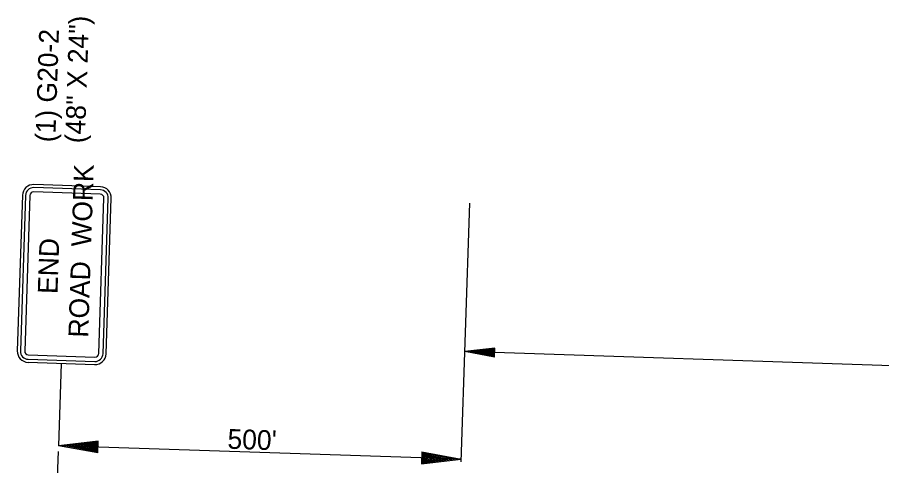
# Model space of a CAD drawing. Extents: x 977269 to 979191, y 1525946 to 1526973.
# Drawn here: x 977812.6 to 978075.3, y 1526710.3 to 1526846.4 of the extents above; entities that cross this region are included whole.
import ezdxf

# ---------------------------------------------------------------- set-up
doc = ezdxf.new("R2010")
doc.units = 0
for name, color, linetype in [('R_Border', 7, 'Continuous'), ('STAMP', 7, 'Continuous'), ('STAMP_PP', 7, 'Continuous')]:
    doc.layers.add(name, color=color, linetype=linetype)

msp = doc.modelspace()

# ---------------------------------------------------------------- linework, layer by layer
at = {"layer": 'STAMP'}
for p, q in [((977947.46, 1526711.49), (977950.08, 1526789.97)), ((977957.68, 1526745.99), (977948.57, 1526744.93)), ((977957.59, 1526743.27), (977948.57, 1526744.93)), ((978256.53, 1526734.66), (977948.57, 1526744.93)), ((977957.67, 1526745.76), (977950.09, 1526744.88)), ((977957.6, 1526743.5), (977950.09, 1526744.88)), ((977957.67, 1526745.53), (977951.65, 1526744.83)), ((977957.61, 1526743.73), (977951.65, 1526744.83)), ((977957.66, 1526745.3), (977953.15, 1526744.78)), ((977957.61, 1526743.95), (977953.15, 1526744.78)), ((977957.65, 1526745.07), (977954.69, 1526744.73)), ((977957.62, 1526744.19), (977954.69, 1526744.73)), ((977957.64, 1526744.84), (977956.2, 1526744.68)), ((977957.63, 1526744.42), (977956.2, 1526744.68)), ((977957.59, 1526743.27), (977957.68, 1526745.99)), ((977826.01, 1526741.35), (977825.18, 1526716.36)), ((977837.2, 1526717.76), (977825.18, 1526716.36)), ((977947.49, 1526712.28), (977825.18, 1526716.36)), ((977837.08, 1526714.17), (977825.18, 1526716.36)), ((977837.19, 1526717.46), (977827.18, 1526716.3)), ((977837.09, 1526714.47), (977827.18, 1526716.3)), ((977837.18, 1526717.15), (977829.24, 1526716.23)), ((977837.1, 1526714.77), (977829.24, 1526716.23)), ((977837.17, 1526716.86), (977831.23, 1526716.16)), ((977837.11, 1526715.07), (977831.23, 1526716.16)), ((977837.16, 1526716.55), (977833.26, 1526716.09)), ((977837.12, 1526715.38), (977833.26, 1526716.09)), ((977837.15, 1526716.24), (977835.25, 1526716.03)), ((977837.13, 1526715.68), (977835.25, 1526716.03)), ((977837.08, 1526714.17), (977837.2, 1526717.76)), ((977824.68, 1526701.15), (977825.13, 1526714.6)), ((977935.58, 1526714.48), (977935.46, 1526710.89)), ((977935.53, 1526712.96), (977937.41, 1526712.62)), ((977935.54, 1526713.26), (977939.41, 1526712.55)), ((977935.55, 1526713.57), (977941.44, 1526712.49)), ((977935.56, 1526713.87), (977943.43, 1526712.42)), ((977935.57, 1526714.18), (977945.49, 1526712.35)), ((977935.58, 1526714.48), (977947.49, 1526712.28)), ((977935.46, 1526710.89), (977947.49, 1526712.28)), ((977935.47, 1526711.19), (977945.49, 1526712.35)), ((977935.48, 1526711.49), (977943.43, 1526712.42)), ((977935.49, 1526711.79), (977941.44, 1526712.49)), ((977935.5, 1526712.1), (977939.41, 1526712.55)), ((977935.51, 1526712.4), (977937.41, 1526712.62))]:
    msp.add_line(p, q, dxfattribs=at)
at = {"layer": 'STAMP_PP'}
for p, q in [((977837.9, 1526794.05), (977817.66, 1526794.72)), ((977837.93, 1526794.98), (977817.69, 1526795.66)), ((977814.21, 1526792.4), (977812.63, 1526745.17)), ((977815.15, 1526792.37), (977813.57, 1526745.14)), ((977816.46, 1526792.32), (977814.88, 1526745.1)), ((977837.86, 1526792.73), (977817.62, 1526793.41)), ((977837.37, 1526744.35), (977838.95, 1526791.57)), ((977838.68, 1526744.3), (977840.26, 1526791.53)), ((977839.62, 1526744.27), (977841.19, 1526791.5)), ((977815.89, 1526741.69), (977836.13, 1526741.01)), ((977815.93, 1526742.62), (977836.16, 1526741.95)), ((977815.97, 1526743.94), (977836.21, 1526743.26))]:
    msp.add_line(p, q, dxfattribs=at)
for centre, radius, start, end in [((977817.58, 1526792.28), 3.37, 88.0901, 178.0901), ((977817.58, 1526792.28), 2.44, 88.0901, 178.0901), ((977837.82, 1526791.61), 3.38, 358.0901, 88.0901), ((977817.58, 1526792.28), 1.13, 88.0901, 178.0901), ((977837.82, 1526791.61), 1.13, 358.0901, 88.0901), ((977837.82, 1526791.61), 2.44, 358.0901, 88.0901), ((977816.01, 1526745.06), 3.38, 178.0901, 268.0901), ((977816.01, 1526745.06), 2.44, 178.0901, 268.0901), ((977816.01, 1526745.06), 1.13, 178.0901, 268.0901), ((977836.25, 1526744.39), 3.37, 268.0901, 358.0901), ((977836.25, 1526744.39), 2.44, 268.0901, 358.0901), ((977836.25, 1526744.39), 1.13, 268.0901, 358.0901)]:
    msp.add_arc(centre, radius, start, end, dxfattribs=at)

# ---------------------------------------------------------------- texts
at = {"layer": 'R_Border'}
for s, p in [('(48" X 24")', (977833.16, 1526808.14)), ('(1) G20-2', (977824.16, 1526808.44))]:
    msp.add_text(s, height=6, rotation=88.0901, dxfattribs=at).set_placement(p)
at = {"layer": 'STAMP'}
msp.add_text("500'", height=6, rotation=358.0901, dxfattribs=at).set_placement((977876.42, 1526715.47))
at = {"layer": 'STAMP_PP'}
for s, p in [('ROAD  WORK', (977834.15, 1526749.12)), ('END', (977824.84, 1526762.37))]:
    msp.add_text(s, height=6, rotation=88.0901, dxfattribs=at).set_placement(p)

doc.saveas('drawing.dxf')
